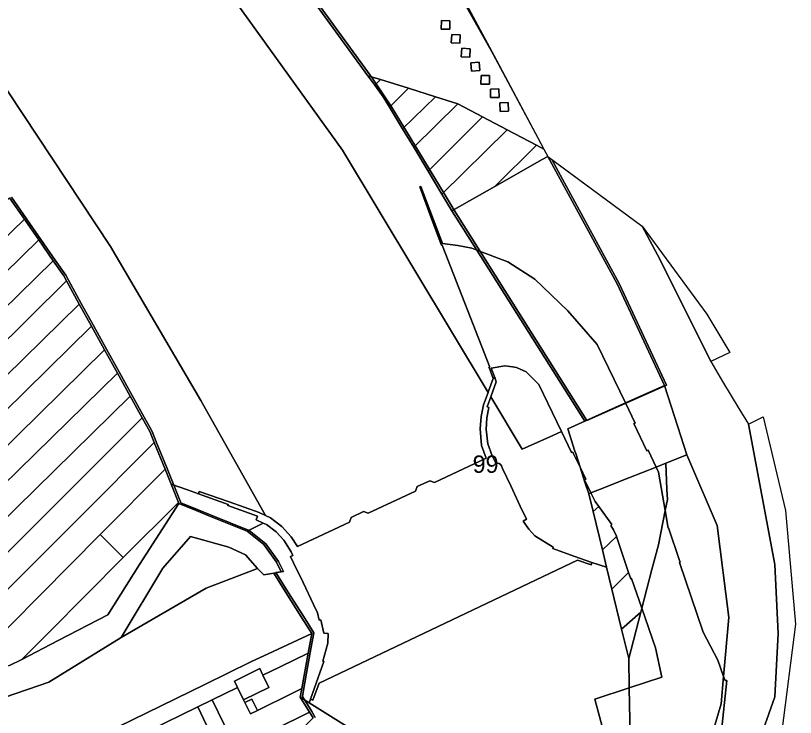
# Model space of a CAD drawing. Extents: x -535894 to -532834, y -1165802 to -1163645.
# Drawn here: x -533201.8 to -532977.3, y -1164904.7 to -1164702.6 of the extents above; entities that cross this region are included whole.
import ezdxf

# ---------------------------------------------------------------- set-up
doc = ezdxf.new("R2010")
doc.units = 0
for name, color, linetype in [('95560013', 7, 'Continuous'), ('95610013', 7, 'Continuous'), ('95630013', 7, 'Continuous'), ('95640013', 7, 'Continuous'), ('95660013', 7, 'Continuous')]:
    doc.layers.add(name, color=color, linetype=linetype)

msp = doc.modelspace()

# ---------------------------------------------------------------- linework, layer by layer
at = {"layer": '95560013'}
for points in [[(-533199.21, -1164761.24), (-533343.76, -1164901.98), (-533353.15, -1164899.58), (-533203.5, -1164755.07)], [(-533195.08, -1164767.19), (-533334.89, -1164904.23), (-533343.76, -1164901.98), (-533199.21, -1164761.24)], [(-533190.93, -1164773.16), (-533324.7, -1164904.32), (-533333.91, -1164904.48), (-533334.89, -1164904.23), (-533195.08, -1164767.19)], [(-533187.91, -1164777.51), (-533187.14, -1164778.93), (-533305.88, -1164896.66), (-533313.39, -1164904.12), (-533324.7, -1164904.32), (-533190.93, -1164773.16)], [(-533183.43, -1164785.63), (-533300.56, -1164900.63), (-533305.88, -1164896.66), (-533187.14, -1164778.93)], [(-533179.93, -1164791.97), (-533293.4, -1164903.76), (-533296.3, -1164903.82), (-533300.56, -1164900.63), (-533183.43, -1164785.63)], [(-533176.14, -1164798.83), (-533282.57, -1164903.56), (-533293.4, -1164903.76), (-533179.93, -1164791.97)], [(-533172.45, -1164805.52), (-533272.33, -1164903.38), (-533282.57, -1164903.56), (-533176.14, -1164798.83)], [(-533168.77, -1164812.17), (-533261.52, -1164903.19), (-533272.33, -1164903.38), (-533172.45, -1164805.52)], [(-533165.34, -1164818.38), (-533229.86, -1164882.85), (-533251.03, -1164902.99), (-533261.52, -1164903.19), (-533168.77, -1164812.17)], [(-533163.04, -1164822.52), (-533161.85, -1164825.47), (-533182.9, -1164846.57), (-533235.8, -1164899.62), (-533249.36, -1164902.96), (-533251.03, -1164902.99), (-533229.86, -1164882.85), (-533165.34, -1164818.38)], [(-533158.74, -1164833.17), (-533177.43, -1164852), (-533220.52, -1164895.43), (-533225.42, -1164897.07), (-533235.8, -1164899.62), (-533182.9, -1164846.57), (-533161.85, -1164825.47)], [(-533156.99, -1164837.52), (-533154.89, -1164842.74), (-533170.75, -1164858.64), (-533177.43, -1164852), (-533158.74, -1164833.17)], [(-533154.75, -1164843.06), (-533166.05, -1164860.58), (-533175.17, -1164875.08), (-533189.49, -1164882.49), (-533200, -1164887.93), (-533192.13, -1164880.06), (-533170.75, -1164858.64), (-533154.89, -1164842.74)], [(-533170.75, -1164858.64), (-533192.13, -1164880.06), (-533200, -1164887.93), (-533203.49, -1164889.74), (-533220.52, -1164895.43), (-533177.43, -1164852)], [(-533149.26, -1164901.65), (-533145.13, -1164899.63), (-533138.32, -1164913.61), (-533119.06, -1164904.11), (-533117.14, -1164903.15), (-533116.11, -1164904.82), (-533137.69, -1164926.13), (-533141.88, -1164917.25)], [(-533149.26, -1164901.65), (-533141.88, -1164917.25), (-533157.58, -1164933.38), (-533260.52, -1165035.2), (-533294.68, -1165069.27), (-533316.06, -1165016.63), (-533241.31, -1164941.86), (-533238.5, -1164941.84), (-533229.28, -1164940.77)]]:
    msp.add_lwpolyline(points, close=True, dxfattribs=at)
at = {"layer": '95610013'}
for points in [[(-533100.33, -1164719.92), (-533096.72, -1164721.02), (-533098.35, -1164722.64)], [(-533098.35, -1164722.64), (-533096.72, -1164721.02), (-533088.71, -1164723.46), (-533094.12, -1164728.97), (-533095.92, -1164725.98)], [(-533088.71, -1164723.46), (-533080.87, -1164725.97), (-533090.4, -1164735.15), (-533094.12, -1164728.97)], [(-533080.87, -1164725.97), (-533074.43, -1164728.01), (-533087.17, -1164740.5), (-533090.4, -1164735.15)], [(-533074.43, -1164728.01), (-533067.33, -1164731.75), (-533083.02, -1164747.39), (-533087.17, -1164740.5)], [(-533067.33, -1164731.75), (-533060.24, -1164735.48), (-533079.04, -1164754), (-533083.02, -1164747.39)], [(-533060.24, -1164735.48), (-533051.79, -1164739.92), (-533063.86, -1164751.81), (-533076.17, -1164758.76), (-533079.04, -1164754)], [(-533051.79, -1164739.92), (-533049.69, -1164741.02), (-533048.53, -1164743.15), (-533050.15, -1164744.07), (-533063.86, -1164751.81)], [(-533050.15, -1164744.07), (-533048.53, -1164743.15), (-533028.64, -1164779.86), (-533014.98, -1164809.1), (-533026.23, -1164814.12), (-533034.33, -1164797.33), (-533042.8, -1164787.55), (-533052.26, -1164778.52), (-533060.06, -1164773.5), (-533068.98, -1164770.15), (-533076.17, -1164758.76), (-533063.86, -1164751.81)]]:
    msp.add_lwpolyline(points, close=True, dxfattribs=at)
at = {"layer": '95630013'}
for points in [[(-533187.88, -1164629.82), (-533107.67, -1164741.3), (-533065.72, -1164811.1), (-533067.05, -1164814.68), (-533067.75, -1164818), (-533068.04, -1164821.56), (-533067.67, -1164826.38), (-533066.32, -1164830), (-533081.23, -1164836.98), (-533082.55, -1164836.49), (-533086.18, -1164838.19), (-533086.66, -1164839.51), (-533100.24, -1164845.86), (-533101.59, -1164845.38), (-533105.21, -1164847.08), (-533105.69, -1164848.41), (-533120.66, -1164855.41), (-533122.43, -1164852.64), (-533125.12, -1164849.67), (-533128.35, -1164847.2), (-533129.85, -1164846.49), (-533148.43, -1164813.4), (-533174.44, -1164769.08), (-533216.56, -1164705.51)], [(-532998.63, -1164909.37), (-532997.02, -1164894.02), (-532997.55, -1164893.98), (-532997.96, -1164892.84), (-532996.43, -1164875.92), (-532999.79, -1164849.41), (-533008.53, -1164829.07), (-533010.27, -1164823.69), (-533013.07, -1164815.01), (-533014.98, -1164809.1), (-533028.64, -1164779.86), (-533048.53, -1164743.15), (-533021.38, -1164763.26), (-533016.19, -1164772.94), (-533001.68, -1164802.19), (-532998.25, -1164807.9), (-532993.57, -1164815.7), (-532990.84, -1164820.26), (-532983.21, -1164860.62), (-532982.29, -1164880.52), (-532983.25, -1164898.77), (-532988.28, -1164913.08)], [(-533203.49, -1164889.74), (-533200, -1164887.93), (-533189.49, -1164882.49), (-533175.17, -1164875.08), (-533166.05, -1164860.58), (-533154.75, -1164843.06), (-533149.77, -1164845.09), (-533146.09, -1164846.58), (-533135.11, -1164851.03), (-533130.34, -1164854.87), (-533126.68, -1164859.92), (-533125.28, -1164862.76), (-533127.47, -1164863.11), (-533130.26, -1164863.56), (-533132.1, -1164861.81), (-533135.59, -1164857.88), (-533140.4, -1164855.68), (-533151.38, -1164852.54), (-533159.38, -1164861.69), (-533171.4, -1164881.68), (-533192.2, -1164894.47), (-533236.41, -1164909.7)], [(-533098.11, -1164912.42), (-533117.22, -1164900.45), (-533116.87, -1164899.42), (-533116.17, -1164899.7), (-533114.4, -1164894.79), (-533040.05, -1164859.4), (-533036.12, -1164860.7), (-533035.87, -1164860.02), (-533031.66, -1164861.43), (-533030.12, -1164867.76), (-533027.33, -1164879.29), (-533025.29, -1164887.7), (-533025.13, -1164896.12), (-533035.02, -1164899.39), (-533024.33, -1164939.46)]]:
    msp.add_lwpolyline(points, dxfattribs=at)
for points in [[(-532990.84, -1164820.26), (-532986.56, -1164818.1), (-532980.17, -1164845.09), (-532977.31, -1164877.84), (-532981.22, -1164908.52), (-532991.79, -1164937.99), (-533005.91, -1164963.1), (-532996.56, -1164936.58), (-532993.75, -1164928.6), (-532988.28, -1164913.08), (-532983.25, -1164898.77), (-532982.29, -1164880.52), (-532983.21, -1164860.62)], [(-533151.38, -1164852.54), (-533140.4, -1164855.68), (-533135.59, -1164857.88), (-533132.1, -1164861.81), (-533146.9, -1164867.45), (-533171.4, -1164881.68), (-533159.38, -1164861.69)]]:
    msp.add_lwpolyline(points, close=True, dxfattribs=at)
at = {"layer": '95640013'}
for points in [[(-533116.98, -1164633.6), (-533101.02, -1164653.29), (-533098.87, -1164655.96), (-533077.99, -1164688.07), (-533051.48, -1164737.74), (-533049.69, -1164741.02), (-533051.79, -1164739.92), (-533060.24, -1164735.48), (-533067.33, -1164731.75), (-533074.43, -1164728.01), (-533080.87, -1164725.97), (-533088.71, -1164723.46), (-533096.72, -1164721.02), (-533100.33, -1164719.92), (-533174.61, -1164617.7), (-533177.92, -1164613.75)], [(-533076.81, -1164704.14), (-533076.81, -1164706.54), (-533079.27, -1164706.54), (-533079.17, -1164704.05)], [(-533076.81, -1164706.54), (-533076.81, -1164704.14), (-533079.17, -1164704.05), (-533079.27, -1164706.54)], [(-533073.82, -1164708.13), (-533073.92, -1164710.55), (-533076.34, -1164710.44), (-533076.21, -1164707.99)], [(-533073.82, -1164708.13), (-533076.21, -1164707.99), (-533076.34, -1164710.44), (-533073.92, -1164710.55)], [(-533070.93, -1164712.12), (-533071, -1164714.53), (-533073.49, -1164714.45), (-533073.36, -1164712)], [(-533070.93, -1164712.12), (-533073.36, -1164712), (-533073.49, -1164714.45), (-533071, -1164714.53)], [(-533068.11, -1164718.44), (-533068.28, -1164716), (-533070.7, -1164716.17), (-533070.53, -1164718.6)], [(-533070.7, -1164716.17), (-533068.28, -1164716), (-533068.11, -1164718.44), (-533070.53, -1164718.6)], [(-533065.35, -1164719.84), (-533067.8, -1164719.85), (-533067.81, -1164722.3), (-533065.35, -1164722.31)], [(-533067.8, -1164719.85), (-533065.35, -1164719.84), (-533065.35, -1164722.31), (-533067.81, -1164722.3)], [(-533062.58, -1164726.19), (-533062.62, -1164723.71), (-533065.05, -1164723.75), (-533065.02, -1164726.21)], [(-533062.62, -1164723.71), (-533062.58, -1164726.19), (-533065.02, -1164726.21), (-533065.05, -1164723.75)], [(-533059.89, -1164730.08), (-533059.99, -1164727.63), (-533062.41, -1164727.74), (-533062.3, -1164730.18)], [(-533059.99, -1164727.63), (-533059.89, -1164730.08), (-533062.3, -1164730.18), (-533062.41, -1164727.74)], [(-533085.42, -1164751.91), (-533085.07, -1164751.78), (-533078.92, -1164768.23), (-533074.48, -1164768.83), (-533070.48, -1164769.59), (-533068.98, -1164770.15), (-533037.94, -1164819.35), (-533042.84, -1164821.55), (-533040.76, -1164827.95), (-533040.53, -1164828.67), (-533039.27, -1164832.6), (-533041.05, -1164828.94), (-533041.39, -1164828.25), (-533041.74, -1164828.4), (-533044.65, -1164822.35), (-533051.13, -1164808.84), (-533054, -1164805.9), (-533054.77, -1164805.11), (-533057.54, -1164803.87), (-533058.72, -1164803.7), (-533060.9, -1164803.39), (-533064.85, -1164804.08), (-533063.85, -1164806.75), (-533064.29, -1164807.07), (-533065.36, -1164804.18), (-533065.5, -1164803.82), (-533065.26, -1164803.77), (-533078.96, -1164768.7), (-533079.18, -1164768.67), (-533079.34, -1164768.17), (-533082.39, -1164760.04)], [(-533016.19, -1164772.94), (-533021.38, -1164763.26), (-533002.77, -1164788.53), (-532996.17, -1164799.59), (-533001.68, -1164802.19)], [(-533068.98, -1164770.15), (-533060.06, -1164773.5), (-533052.26, -1164778.52), (-533042.8, -1164787.55), (-533034.33, -1164797.33), (-533026.23, -1164814.12), (-533037.94, -1164819.35)], [(-533058.72, -1164803.7), (-533057.54, -1164803.87), (-533054.77, -1164805.11), (-533054, -1164805.9), (-533051.13, -1164808.84), (-533044.65, -1164822.35), (-533047.16, -1164823.47), (-533055.93, -1164827.39), (-533064.98, -1164812.34), (-533063.41, -1164808.03), (-533063.85, -1164806.75), (-533064.85, -1164804.08), (-533060.9, -1164803.39)], [(-533063.85, -1164806.75), (-533063.41, -1164808.03), (-533064.98, -1164812.34), (-533066.05, -1164815.28), (-533065.52, -1164815.47), (-533066.12, -1164818.42), (-533066.32, -1164821.75), (-533065.88, -1164825.93), (-533064.62, -1164829.31), (-533063.56, -1164831.41), (-533063.04, -1164831.41), (-533062.61, -1164831.54), (-533062.18, -1164831.87), (-533061.94, -1164832.22), (-533061.6, -1164832.94), (-533059.24, -1164838), (-533056.49, -1164843.86), (-533054.66, -1164847.53), (-533055.68, -1164848.17), (-533054.08, -1164850.46), (-533052.32, -1164852.42), (-533047, -1164855.6), (-533047.16, -1164856.06), (-533041.04, -1164858.27), (-533035.87, -1164860.02), (-533036.12, -1164860.7), (-533040.05, -1164859.4), (-533114.4, -1164894.79), (-533116.17, -1164899.7), (-533116.87, -1164899.42), (-533113.01, -1164888.56), (-533113.29, -1164888.46), (-533111.9, -1164883.32), (-533111.8, -1164880.45), (-533113, -1164880.39), (-533113.94, -1164876.55), (-533114.4, -1164876.67), (-533114.81, -1164874.57), (-533116.02, -1164872.19), (-533119.01, -1164865.81), (-533121.79, -1164860.11), (-533122.6, -1164858.35), (-533121.94, -1164858.07), (-533122.39, -1164856.98), (-533124.52, -1164853.64), (-533126.75, -1164851.21), (-533129.49, -1164849.15), (-533130.46, -1164848.72), (-533132.52, -1164847.81), (-533132.11, -1164846.71), (-533140.65, -1164843.63), (-533140.54, -1164843.32), (-533149.14, -1164840.29), (-533148.9, -1164839.58), (-533140.25, -1164842.55), (-533131.61, -1164845.66), (-533129.85, -1164846.49), (-533128.35, -1164847.2), (-533125.12, -1164849.67), (-533122.43, -1164852.64), (-533120.66, -1164855.41), (-533105.69, -1164848.41), (-533105.21, -1164847.08), (-533101.59, -1164845.38), (-533100.24, -1164845.86), (-533086.66, -1164839.51), (-533086.18, -1164838.19), (-533082.55, -1164836.49), (-533081.23, -1164836.98), (-533066.32, -1164830), (-533067.67, -1164826.38), (-533068.04, -1164821.56), (-533067.75, -1164818), (-533067.05, -1164814.68), (-533065.72, -1164811.1), (-533065.61, -1164810.76), (-533064.29, -1164807.07)], [(-533014.98, -1164809.1), (-533013.07, -1164815.01), (-533010.27, -1164823.69), (-533008.53, -1164829.07), (-533014.61, -1164831.49), (-533017.38, -1164832.62), (-533019.64, -1164827.73), (-533020.06, -1164827.93), (-533023.77, -1164820.07), (-533023.43, -1164819.91), (-533026.23, -1164814.12)], [(-533064.98, -1164812.34), (-533055.93, -1164827.39), (-533047.16, -1164823.47), (-533044.65, -1164822.35), (-533041.74, -1164828.4), (-533041.39, -1164828.25), (-533041.05, -1164828.94), (-533039.27, -1164832.6), (-533037.87, -1164836.9), (-533036.78, -1164840.28), (-533035.54, -1164845.41), (-533032.87, -1164856.43), (-533031.66, -1164861.43), (-533035.87, -1164860.02), (-533041.04, -1164858.27), (-533047.16, -1164856.06), (-533047, -1164855.6), (-533052.32, -1164852.42), (-533054.08, -1164850.46), (-533055.68, -1164848.17), (-533054.66, -1164847.53), (-533056.49, -1164843.86), (-533059.24, -1164838), (-533061.6, -1164832.94), (-533061.94, -1164832.22), (-533062.18, -1164831.87), (-533062.61, -1164831.54), (-533063.04, -1164831.41), (-533063.56, -1164831.41), (-533064.62, -1164829.31), (-533065.88, -1164825.93), (-533066.32, -1164821.75), (-533066.12, -1164818.42), (-533065.52, -1164815.47), (-533066.05, -1164815.28)], [(-533026.23, -1164814.12), (-533023.43, -1164819.91), (-533023.77, -1164820.07), (-533020.06, -1164827.93), (-533019.64, -1164827.73), (-533017.38, -1164832.62), (-533025.28, -1164835.72), (-533033.7, -1164839.05), (-533036.16, -1164840.03), (-533037.98, -1164836.23), (-533037.58, -1164836.04), (-533039.27, -1164832.6), (-533040.53, -1164828.67), (-533040.76, -1164827.95), (-533042.84, -1164821.55), (-533037.94, -1164819.35)], [(-533008.53, -1164829.07), (-532999.79, -1164849.41), (-532996.43, -1164875.92), (-532997.96, -1164892.84), (-532999.62, -1164888.13), (-533003.87, -1164880.13), (-533010.66, -1164860.03), (-533010.45, -1164859.97), (-533010.63, -1164859.43), (-533013.81, -1164850.1), (-533013.9, -1164850.14), (-533014.78, -1164845.11), (-533014.15, -1164841.92), (-533014.28, -1164839.02), (-533014.61, -1164831.49)], [(-533014.61, -1164831.49), (-533014.28, -1164839.02), (-533014.15, -1164841.92), (-533014.78, -1164845.11), (-533016.73, -1164834.02), (-533017.38, -1164832.62)], [(-533037.58, -1164836.04), (-533037.98, -1164836.23), (-533036.16, -1164840.03), (-533036.78, -1164840.28), (-533037.87, -1164836.9), (-533039.27, -1164832.6)], [(-533017.38, -1164832.62), (-533016.73, -1164834.02), (-533014.78, -1164845.11), (-533016.75, -1164854.92), (-533018.63, -1164862.11), (-533021.51, -1164873.18), (-533024.46, -1164864.68), (-533024.68, -1164864.75), (-533025.3, -1164862.89), (-533028.77, -1164852.59), (-533028.81, -1164852.46), (-533029.63, -1164850.67), (-533030.47, -1164849.39), (-533030.1, -1164849.13), (-533033.92, -1164843.89), (-533034.93, -1164842.51), (-533036.16, -1164840.03), (-533033.7, -1164839.05), (-533025.28, -1164835.72)], [(-533152.31, -1164839.17), (-533149.14, -1164840.29), (-533140.54, -1164843.32), (-533140.65, -1164843.63), (-533132.11, -1164846.71), (-533132.52, -1164847.81), (-533130.46, -1164848.72), (-533135.11, -1164851.03), (-533146.09, -1164846.58), (-533149.77, -1164845.09), (-533154.75, -1164843.06), (-533154.89, -1164842.74), (-533156.99, -1164837.52)], [(-533036.16, -1164840.03), (-533034.93, -1164842.51), (-533033.92, -1164843.89), (-533035.54, -1164845.41), (-533036.78, -1164840.28)], [(-533035.54, -1164845.41), (-533033.92, -1164843.89), (-533030.1, -1164849.13), (-533030.47, -1164849.39), (-533029.63, -1164850.67), (-533028.81, -1164852.46), (-533028.77, -1164852.59), (-533032.87, -1164856.43)], [(-533013.9, -1164850.14), (-533013.81, -1164850.1), (-533010.63, -1164859.43), (-533010.45, -1164859.97), (-533010.66, -1164860.03), (-533003.87, -1164880.13), (-532999.62, -1164888.13), (-532997.96, -1164892.84), (-532998.67, -1164900.76), (-533005.49, -1164923.73), (-533009.67, -1164931.84), (-533010.36, -1164932.29), (-533012.47, -1164933.65), (-533014.17, -1164935.04), (-533016.06, -1164937.15), (-533024.33, -1164939.46), (-533024.62, -1164923.92), (-533025.13, -1164896.12), (-533015.73, -1164893.02), (-533017.56, -1164884.6), (-533021.51, -1164873.18), (-533018.63, -1164862.11), (-533016.75, -1164854.92), (-533014.78, -1164845.11)], [(-533129.49, -1164849.15), (-533126.75, -1164851.21), (-533124.52, -1164853.64), (-533122.39, -1164856.98), (-533121.94, -1164858.07), (-533122.6, -1164858.35), (-533121.79, -1164860.11), (-533119.01, -1164865.81), (-533116.02, -1164872.19), (-533114.81, -1164874.57), (-533114.4, -1164876.67), (-533113.94, -1164876.55), (-533113, -1164880.39), (-533111.8, -1164880.45), (-533111.9, -1164883.32), (-533113.29, -1164888.46), (-533113.01, -1164888.56), (-533116.87, -1164899.42), (-533117.22, -1164900.45), (-533119.82, -1164898.82), (-533119.37, -1164896.37), (-533117.54, -1164886.14), (-533116.52, -1164880.45), (-533119.52, -1164875.7), (-533123.98, -1164868.64), (-533127.47, -1164863.11), (-533125.28, -1164862.76), (-533126.68, -1164859.92), (-533130.34, -1164854.87), (-533135.11, -1164851.03), (-533130.46, -1164848.72)], [(-533032.87, -1164856.43), (-533028.77, -1164852.59), (-533025.3, -1164862.89), (-533030.12, -1164867.76), (-533031.66, -1164861.43)], [(-533024.46, -1164864.68), (-533021.51, -1164873.18), (-533021.81, -1164874.35), (-533027.33, -1164879.29), (-533030.12, -1164867.76), (-533025.3, -1164862.89), (-533024.68, -1164864.75)], [(-533027.33, -1164879.29), (-533021.81, -1164874.35), (-533025.29, -1164887.7)], [(-533021.81, -1164874.35), (-533021.51, -1164873.18), (-533017.56, -1164884.6), (-533015.73, -1164893.02), (-533025.13, -1164896.12), (-533025.29, -1164887.7)], [(-533125.56, -1164890.06), (-533117.54, -1164886.14), (-533119.37, -1164896.37), (-533122.04, -1164897.68), (-533132.1, -1164902.62), (-533133.74, -1164899.4), (-533135.74, -1164900.39), (-533136.13, -1164899.58), (-533128.85, -1164896.01), (-533130.56, -1164892.51)], [(-533131.5, -1164890.61), (-533130.56, -1164892.51), (-533128.85, -1164896.01), (-533136.13, -1164899.58), (-533137.86, -1164896.07), (-533138.79, -1164894.19)], [(-532997.96, -1164892.84), (-532997.55, -1164893.98), (-532997.02, -1164894.02), (-532998.63, -1164909.37), (-532994.46, -1164920.43), (-532998.95, -1164924.85), (-533001.85, -1164927.06), (-533003.92, -1164928.32), (-533006.56, -1164929.76), (-533009.67, -1164931.84), (-533005.49, -1164923.73), (-532998.67, -1164900.76)], [(-533122.04, -1164897.68), (-533119.37, -1164896.37), (-533119.82, -1164898.82), (-533117.14, -1164903.15), (-533119.06, -1164904.11), (-533138.32, -1164913.61), (-533145.13, -1164899.63), (-533137.86, -1164896.07), (-533136.13, -1164899.58), (-533135.74, -1164900.39), (-533134.16, -1164903.63), (-533132.1, -1164902.62)], [(-533035.02, -1164899.39), (-533025.13, -1164896.12), (-533024.62, -1164923.92), (-533024.33, -1164939.46)], [(-533135.74, -1164900.39), (-533133.74, -1164899.4), (-533132.1, -1164902.62), (-533134.16, -1164903.63)]]:
    msp.add_lwpolyline(points, close=True, dxfattribs=at)
for points in [[(-533174.61, -1164617.7), (-533100.33, -1164719.92), (-533098.35, -1164722.64), (-533095.92, -1164725.98), (-533094.12, -1164728.97), (-533090.4, -1164735.15), (-533087.17, -1164740.5), (-533083.02, -1164747.39), (-533079.04, -1164754), (-533076.17, -1164758.76), (-533068.98, -1164770.15), (-533070.48, -1164769.59), (-533074.48, -1164768.83), (-533078.92, -1164768.23), (-533085.07, -1164751.78), (-533085.42, -1164751.91), (-533082.39, -1164760.04), (-533079.34, -1164768.17), (-533079.18, -1164768.67), (-533078.96, -1164768.7), (-533065.26, -1164803.77), (-533065.5, -1164803.82), (-533065.36, -1164804.18), (-533064.29, -1164807.07), (-533065.61, -1164810.76), (-533065.72, -1164811.1), (-533107.67, -1164741.3), (-533187.88, -1164629.82)], [(-533216.56, -1164705.51), (-533174.44, -1164769.08), (-533148.43, -1164813.4), (-533129.85, -1164846.49), (-533131.61, -1164845.66), (-533140.25, -1164842.55), (-533148.9, -1164839.58), (-533149.14, -1164840.29), (-533152.31, -1164839.17), (-533156.99, -1164837.52), (-533158.74, -1164833.17), (-533161.85, -1164825.47), (-533163.04, -1164822.52), (-533165.34, -1164818.38), (-533168.77, -1164812.17), (-533172.45, -1164805.52), (-533176.14, -1164798.83), (-533179.93, -1164791.97), (-533183.43, -1164785.63), (-533187.14, -1164778.93), (-533187.91, -1164777.51), (-533190.93, -1164773.16), (-533195.08, -1164767.19), (-533199.21, -1164761.24), (-533203.5, -1164755.07)], [(-533236.41, -1164909.7), (-533192.2, -1164894.47), (-533171.4, -1164881.68), (-533146.9, -1164867.45), (-533132.1, -1164861.81), (-533130.26, -1164863.56), (-533127.47, -1164863.11), (-533123.98, -1164868.64), (-533119.52, -1164875.7), (-533116.52, -1164880.45), (-533127.62, -1164885.63), (-533134.02, -1164888.62), (-533147.32, -1164895.13), (-533230.7, -1164935.9)], [(-533230.7, -1164935.9), (-533147.32, -1164895.13), (-533134.02, -1164888.62), (-533127.62, -1164885.63), (-533116.52, -1164880.45), (-533117.54, -1164886.14), (-533125.56, -1164890.06), (-533130.56, -1164892.51), (-533131.5, -1164890.61), (-533138.79, -1164894.19), (-533137.86, -1164896.07), (-533145.13, -1164899.63), (-533149.26, -1164901.65), (-533229.28, -1164940.77)], [(-533116.11, -1164904.82), (-533117.14, -1164903.15), (-533119.82, -1164898.82), (-533117.22, -1164900.45), (-533098.11, -1164912.42)]]:
    msp.add_lwpolyline(points, dxfattribs=at)
at = {"layer": '95660013'}
msp.add_lwpolyline([(-533064.041, -1164714.206), (-533051.48, -1164737.74), (-533049.69, -1164741.02), (-533048.53, -1164743.15), (-533047.398, -1164743.989), (-533028.041, -1164779.71), (-533014.38, -1164808.947), (-533037.332, -1164819.2), (-533075.566, -1164758.607), (-533078.437, -1164753.841), (-533082.42, -1164747.231), (-533086.574, -1164740.34), (-533089.802, -1164734.991), (-533093.522, -1164728.812), (-533097.748, -1164722.487), (-533099.729, -1164719.761), (-533174.02, -1164617.541), (-533177.323, -1164613.591), (-533144.122, -1164624.407), (-533120.195, -1164632.203), (-533112.188, -1164642.002), (-533098.703, -1164658.507), (-533086.643, -1164676.675), (-533076.582, -1164691.833)], close=True, dxfattribs=at)
for points in [[(-533174.02, -1164617.541), (-533099.729, -1164719.761), (-533097.748, -1164722.487), (-533093.522, -1164728.812), (-533089.802, -1164734.991), (-533086.574, -1164740.34), (-533082.42, -1164747.231), (-533078.437, -1164753.841), (-533075.566, -1164758.607), (-533037.332, -1164819.2), (-533014.38, -1164808.947), (-533028.041, -1164779.71), (-533047.398, -1164743.989), (-533021.38, -1164763.26), (-533002.77, -1164788.53), (-532996.17, -1164799.59), (-533001.68, -1164802.19), (-532998.25, -1164807.9), (-532993.57, -1164815.7), (-532990.84, -1164820.26), (-532986.56, -1164818.1), (-532980.17, -1164845.09), (-532977.31, -1164877.84), (-532981.22, -1164908.52)], [(-533077.99, -1164688.07), (-533064.041, -1164714.206), (-533076.582, -1164691.833)], [(-533202.897, -1164754.903), (-533198.613, -1164761.074), (-533194.476, -1164767.027), (-533190.332, -1164773.001), (-533187.314, -1164777.351), (-533186.536, -1164778.766), (-533182.834, -1164785.465), (-533179.324, -1164791.812), (-533175.539, -1164798.672), (-533171.846, -1164805.359), (-533168.169, -1164812.007), (-533164.734, -1164818.214), (-533162.439, -1164822.363), (-533161.248, -1164825.312), (-533158.139, -1164833.012), (-533154.284, -1164842.576), (-533154.149, -1164842.903), (-533149.163, -1164844.927), (-533145.487, -1164846.423), (-533134.501, -1164850.874), (-533129.737, -1164854.714), (-533126.072, -1164859.76), (-533124.678, -1164862.601), (-533126.87, -1164862.951), (-533123.37, -1164868.48), (-533118.912, -1164875.536), (-533115.91, -1164880.287), (-533116.935, -1164885.978), (-533118.768, -1164896.207), (-533119.211, -1164898.663), (-533116.533, -1164902.995), (-533115.501, -1164904.659)], [(-533115.501, -1164904.659), (-533116.533, -1164902.995), (-533119.211, -1164898.663), (-533118.768, -1164896.207), (-533116.935, -1164885.978), (-533115.91, -1164880.287), (-533118.912, -1164875.536), (-533123.37, -1164868.48), (-533126.87, -1164862.951), (-533124.678, -1164862.601), (-533126.072, -1164859.76), (-533129.737, -1164854.714), (-533134.501, -1164850.874), (-533145.487, -1164846.423), (-533149.163, -1164844.927), (-533154.149, -1164842.903), (-533154.284, -1164842.576), (-533158.139, -1164833.012), (-533161.248, -1164825.312), (-533162.439, -1164822.363), (-533164.734, -1164818.214), (-533168.169, -1164812.007), (-533171.846, -1164805.359), (-533175.539, -1164798.672), (-533179.324, -1164791.812), (-533182.834, -1164785.465), (-533186.536, -1164778.766), (-533187.314, -1164777.351), (-533190.332, -1164773.001), (-533194.476, -1164767.027), (-533198.613, -1164761.074), (-533202.897, -1164754.903)]]:
    msp.add_lwpolyline(points, dxfattribs=at)

# ---------------------------------------------------------------- texts
msp.add_text('99', height=5, rotation=0, dxfattribs=at).set_placement((-533070.195, -1164834.23))

doc.saveas('drawing.dxf')
